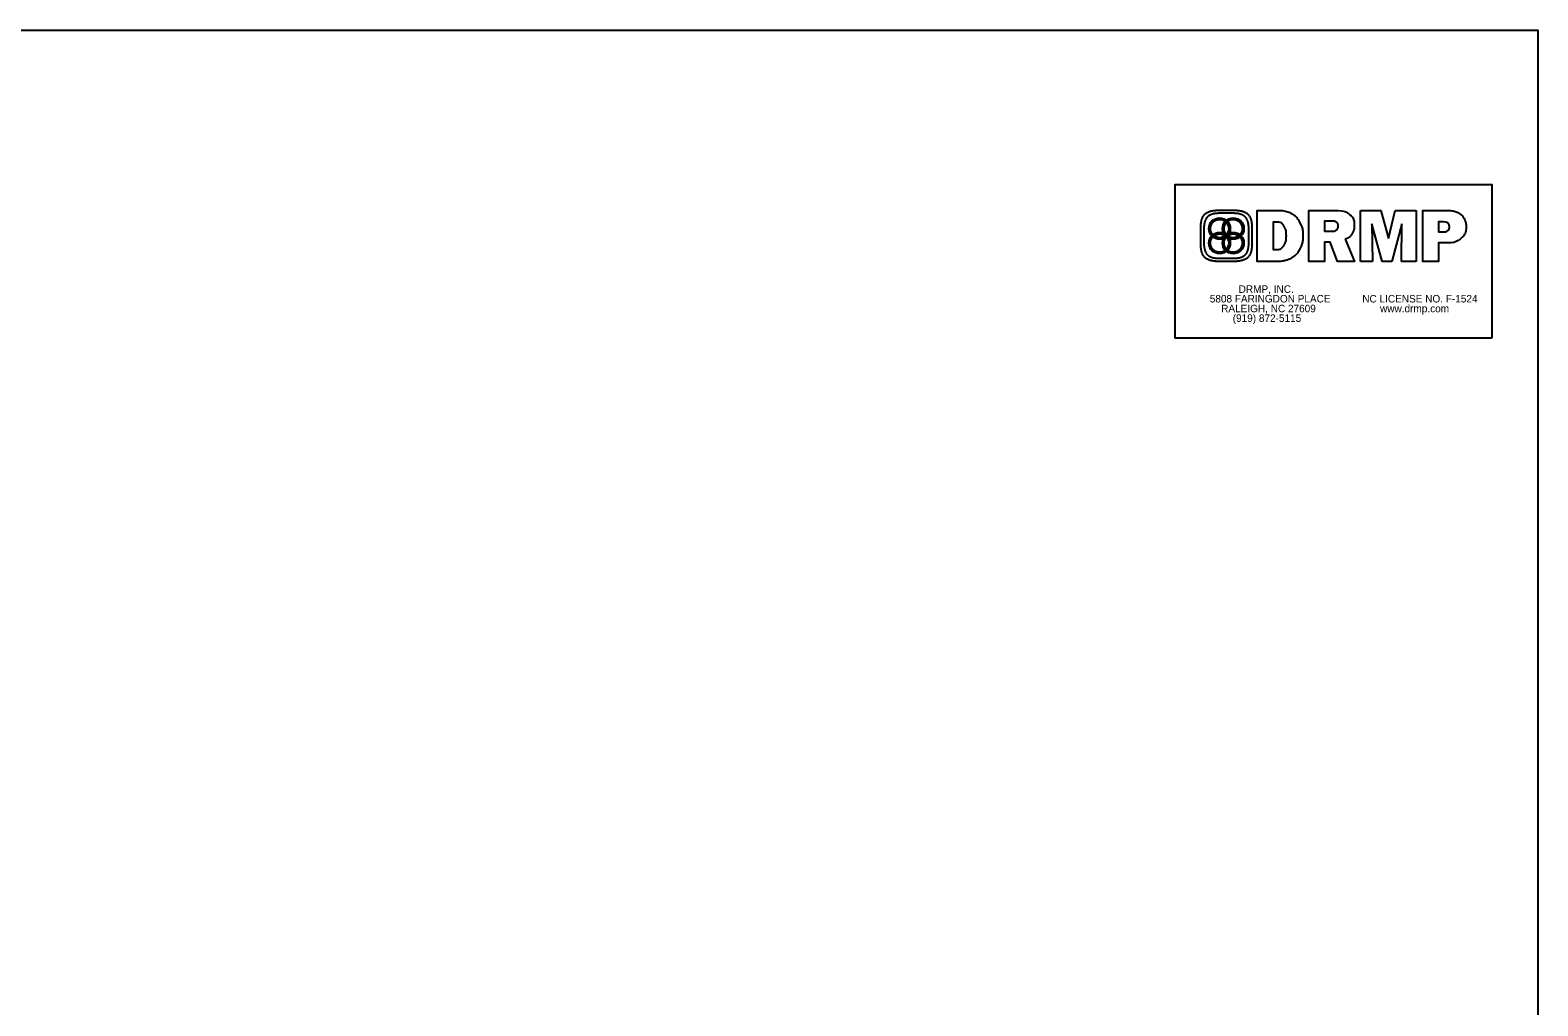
# Model space of a CAD drawing. Extents: x 0.07 to 2.11, y -2.58 to -1.26.
import ezdxf

# ---------------------------------------------------------------- set-up
doc = ezdxf.new("R2010")
doc.units = 0
for name, color, linetype in [('Pattern 1', 7, 'Continuous'), ('Pattern 2', 7, 'Continuous'), ('Sheet Plan CELL', 7, 'Continuous'), ('Sheet Plot Border Inside CELL', 7, 'Continuous')]:
    doc.layers.add(name, color=color, linetype=linetype)

msp = doc.modelspace()

# ---------------------------------------------------------------- linework, layer by layer
at = {"layer": 'Pattern 1'}
for p, q in [((1.8934, -1.3842), (1.9034, -1.3842)), ((1.989, -1.4189), (1.989, -1.3843)), ((1.989, -1.3843), (2.0026, -1.3843)), ((2.0026, -1.3843), (2.0078, -1.4032)), ((2.0078, -1.4032), (2.0124, -1.3843)), ((2.0124, -1.3843), (2.0266, -1.3843)), ((2.0266, -1.3843), (2.0266, -1.4189)), ((1.9028, -1.3863), (1.894, -1.3863)), ((2.0035, -1.4189), (1.9967, -1.3935)), ((1.9967, -1.3935), (1.9971, -1.4189)), ((2.0168, -1.3935), (2.0102, -1.4189)), ((2.0166, -1.4189), (2.0168, -1.3935)), ((1.8811, -1.4065), (1.8811, -1.3965)), ((1.8832, -1.3971), (1.8832, -1.4059)), ((1.9136, -1.4059), (1.9136, -1.3971)), ((1.9157, -1.3965), (1.9157, -1.4065)), ((1.9034, -1.4188), (1.8934, -1.4188)), ((1.894, -1.4167), (1.9028, -1.4167)), ((1.9971, -1.4189), (1.989, -1.4189)), ((2.0102, -1.4189), (2.0035, -1.4189)), ((2.0266, -1.4189), (2.0166, -1.4189))]:
    msp.add_line(p, q, dxfattribs=at)
for points in [[(1.9321, -1.4189), (1.9193, -1.4189), (1.9193, -1.3843), (1.9326, -1.3843)], [(1.9787, -1.4038), (1.9849, -1.4189), (1.9735, -1.4189), (1.9684, -1.4058), (1.9647, -1.4058), (1.9647, -1.4189), (1.9542, -1.4189), (1.9542, -1.3843), (1.9711, -1.3843)], [(2.0478, -1.4063), (2.0416, -1.4063), (2.0416, -1.4189), (2.031, -1.4189), (2.031, -1.3843), (2.0458, -1.3843)], [(1.9326, -1.3922), (1.9299, -1.3922), (1.9299, -1.4108), (1.9323, -1.4108)], [(1.9696, -1.3916), (1.9647, -1.3916), (1.9647, -1.3984), (1.9698, -1.3984)], [(2.0451, -1.3921), (2.0416, -1.3921), (2.0416, -1.3989), (2.0445, -1.3989)]]:
    msp.add_lwpolyline(points, dxfattribs=at)
for points, degree in [([(1.8811, -1.3965), (1.8811, -1.3897), (1.8866, -1.3842), (1.8934, -1.3842)], 2), ([(1.9034, -1.3842), (1.9102, -1.3842), (1.9157, -1.3897), (1.9157, -1.3965)], 2), ([(1.9326, -1.3843), (1.9347, -1.3843), (1.9366, -1.3844), (1.9382, -1.3848), (1.9399, -1.3852), (1.9413, -1.3858), (1.9426, -1.3865), (1.945, -1.388), (1.9468, -1.3901), (1.9481, -1.3927), (1.9494, -1.3953), (1.9501, -1.3983), (1.9501, -1.4016), (1.9501, -1.4044), (1.9495, -1.4072), (1.9483, -1.4097), (1.9472, -1.4122), (1.9456, -1.4142), (1.9436, -1.4157), (1.9421, -1.4168), (1.9405, -1.4176), (1.9386, -1.4181), (1.9368, -1.4186), (1.9346, -1.4189), (1.9321, -1.4189)], 3), ([(1.9711, -1.3843), (1.9757, -1.3843), (1.9791, -1.3851), (1.9813, -1.3868), (1.9836, -1.3885), (1.9847, -1.391), (1.9847, -1.3944), (1.9847, -1.3967), (1.9842, -1.3987), (1.9832, -1.4003), (1.9821, -1.4019), (1.9806, -1.4031), (1.9787, -1.4038)], 3), ([(2.0458, -1.3843), (2.0481, -1.3843), (2.05, -1.3844), (2.0515, -1.3847), (2.053, -1.385), (2.0543, -1.3854), (2.0553, -1.386), (2.0569, -1.3871), (2.0582, -1.3883), (2.059, -1.3899), (2.0598, -1.3915), (2.0603, -1.3932), (2.0603, -1.3952), (2.0603, -1.3985), (2.0591, -1.4012), (2.0568, -1.4032), (2.0545, -1.4053), (2.0515, -1.4063), (2.0478, -1.4063)], 3), ([(1.894, -1.3863), (1.8881, -1.3863), (1.8832, -1.3912), (1.8832, -1.3971)], 2), ([(1.9136, -1.3971), (1.9136, -1.3912), (1.9087, -1.3863), (1.9028, -1.3863)], 2), ([(1.9323, -1.4108), (1.9343, -1.4108), (1.9359, -1.4099), (1.9371, -1.4082), (1.9383, -1.4065), (1.9389, -1.4042), (1.9389, -1.4014), (1.9389, -1.3986), (1.9383, -1.3964), (1.9372, -1.3947), (1.936, -1.393), (1.9345, -1.3922), (1.9326, -1.3922)], 3), ([(1.9698, -1.3984), (1.971, -1.3984), (1.972, -1.3981), (1.9728, -1.3975), (1.9736, -1.3968), (1.974, -1.396), (1.974, -1.395), (1.974, -1.3939), (1.9736, -1.393), (1.9729, -1.3925), (1.9722, -1.3919), (1.9711, -1.3916), (1.9696, -1.3916)], 3), ([(2.0445, -1.3989), (2.0459, -1.3989), (2.047, -1.3986), (2.0478, -1.398), (2.0486, -1.3974), (2.049, -1.3965), (2.049, -1.3955), (2.049, -1.3944), (2.0487, -1.3935), (2.048, -1.393), (2.0474, -1.3924), (2.0464, -1.3921), (2.0451, -1.3921)], 3), ([(1.8934, -1.4188), (1.8866, -1.4188), (1.8811, -1.4133), (1.8811, -1.4065)], 2), ([(1.8832, -1.4059), (1.8832, -1.4119), (1.8881, -1.4167), (1.894, -1.4167)], 2), ([(1.9028, -1.4167), (1.9087, -1.4167), (1.9136, -1.4119), (1.9136, -1.4059)], 2), ([(1.9157, -1.4065), (1.9157, -1.4133), (1.9102, -1.4188), (1.9034, -1.4188)], 2)]:
    msp.add_open_spline(points, degree=degree, dxfattribs=at)
at = {"layer": 'Pattern 2'}
for centre, radius in [((1.8938, -1.3966), 0.00724), ((1.8938, -1.3966), 0.00616), ((1.903, -1.3966), 0.00724), ((1.903, -1.3966), 0.00616), ((1.8938, -1.4064), 0.00724), ((1.8938, -1.4064), 0.00616), ((1.903, -1.4064), 0.00724), ((1.903, -1.4064), 0.00616)]:
    msp.add_circle(centre, radius, dxfattribs=at)
at = {"layer": 'Sheet Plan CELL'}
msp.add_lwpolyline([(2.0776, -1.4705), (1.8638, -1.4705), (1.8638, -1.3669), (2.0776, -1.3669)], close=True, dxfattribs=at)
at = {"layer": 'Sheet Plot Border Inside CELL'}
msp.add_lwpolyline([(0.0726, -1.2626), (2.1087, -1.2626), (2.1087, -2.5802), (0.0726, -2.5802)], close=True, dxfattribs=at)

# ---------------------------------------------------------------- texts
at = {"layer": 'Pattern 2'}
for s, height, p in [('DRMP, INC.', 0.00506, (1.9067, -1.44)), ('5808 FARINGDON PLACE', 0.005058, (1.8872, -1.4465)), ('NC LICENSE NO. F-1524', 0.005058, (1.9902, -1.4465)), ('RALEIGH, NC 27609', 0.005058, (1.8949, -1.4531)), ('(919) 872-5115', 0.005058, (1.9027, -1.4596)), ('www.drmp.com', 0.005058, (2.0022, -1.4531))]:
    msp.add_text(s, height=height, rotation=360, dxfattribs=at).set_placement(p)

doc.saveas('drawing.dxf')
